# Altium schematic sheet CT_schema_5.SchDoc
size 298 x 247 mm
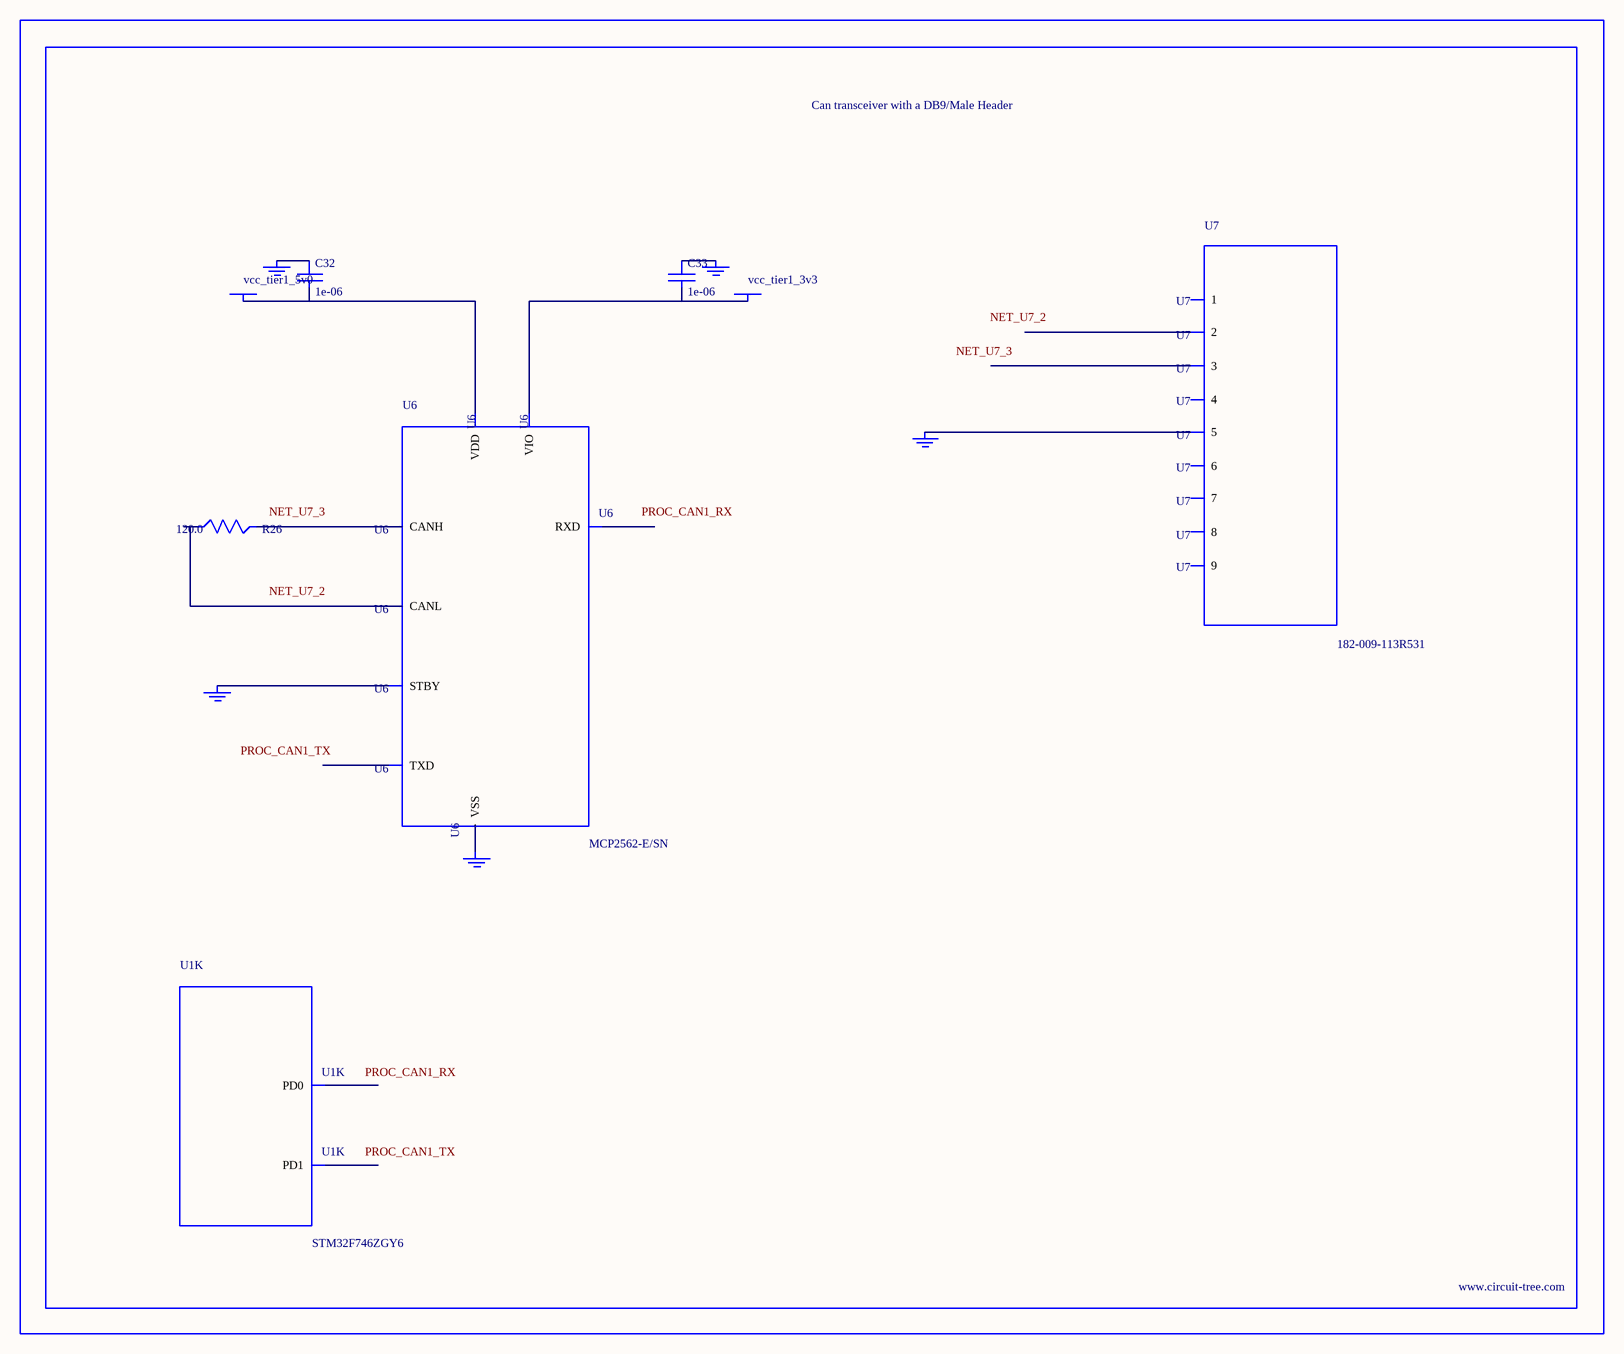
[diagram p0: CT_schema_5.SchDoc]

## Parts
BORDER4  (no value)
C32  1e-06  [C0603]
C33  1e-06  [C0603]
GND_INSTANCE_4_0  (no value)
GND_INSTANCE_4_1  (no value)
GND_INSTANCE_4_2  (no value)
GND_INSTANCE_4_3  (no value)
GND_INSTANCE_4_4  (no value)
POWER_INSTANCE_4_0  vcc_tier1_5v0
POWER_INSTANCE_4_1  vcc_tier1_3v3
R26  120.0  [R0603]
U1  STM32F746ZGY6  [WLCSP143]  (part K of 13)
U6  MCP2562-E/SN  [SOIC-8]
U7  182-009-113R531  [182-009-MALE]

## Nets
NetC32_1: C32.1 GND_INSTANCE_4_0.0(GND)
NetC32_2: C32.2 POWER_INSTANCE_4_0.0(PWR) U6.3(VDD)
NetC33_1: C33.1 GND_INSTANCE_4_1.0(GND)
NetC33_2: C33.2 POWER_INSTANCE_4_1.0(PWR) U6.5(VIO)
NetGND_INSTANCE_4_2_0: GND_INSTANCE_4_2.0(GND) U6.8(STBY)
NetGND_INSTANCE_4_3_0: GND_INSTANCE_4_3.0(GND) U6.2(VSS)
NetGND_INSTANCE_4_4_0: GND_INSTANCE_4_4.0(GND) U7.5
NetR26_1: R26.1 U6.6(CANL)
NetR26_2: R26.2 U6.7(CANH)

Not connected (* = marked no-connect by the designer): U1 B3(PD0) C4(PD1); U6 1(TXD) 4(RXD); U7 1 2 3 4 6 7 8 9

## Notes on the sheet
- Labels drawn without touching a wire or pin: NET_U7_2, NET_U7_3, PROC_CAN1_RX, PROC_CAN1_TX

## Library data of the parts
BORDER4 = BORDER_PAGE4
C32 C33 = C0603C105K3RACTU
GND_INSTANCE_4_0-GND_INSTANCE_4_4 = GND
POWER_INSTANCE_4_0 POWER_INSTANCE_4_1 = PWR
R26 = RC0603JR-07120RL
